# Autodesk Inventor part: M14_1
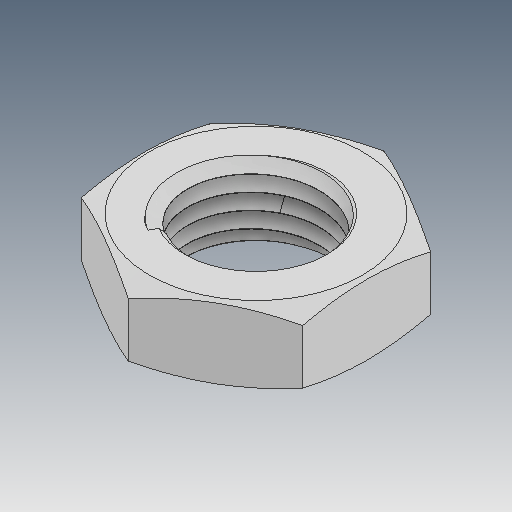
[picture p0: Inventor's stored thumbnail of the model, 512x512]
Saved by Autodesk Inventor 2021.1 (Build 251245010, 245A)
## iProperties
Created: 2019-04
Part Number: M14_1
Material: Ogólny
Document SubType Name: Modeling
Designer: user
Density: 1 g/cm^3
Appearance: Domyślna
Author: user
Revision Number: ÈÎºÎ
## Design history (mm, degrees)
feature "ÊäÈë1"
node "Bryła1"
